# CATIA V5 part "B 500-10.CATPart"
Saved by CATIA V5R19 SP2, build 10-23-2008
Part number: B 500-10
Bounding box of the stored display mesh (mm): x -18.951 to 18.951, y -18.952 to 18.952, z 0 to 70
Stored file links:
  C:\Users\Bora\Desktop\3D Katı model\B serisi\B 500\B 500-10.CATPart
  C:\Program Files\Dassault Systemes\B19\intel_a\reffiles\standard\MetricThickPitch.txt
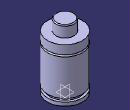
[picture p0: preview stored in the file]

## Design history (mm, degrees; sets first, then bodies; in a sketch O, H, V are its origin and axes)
Body1 (main body)
  Sketch1 on yz-plane, origin (0, 0, 0), H (0, 1, 0), V (0, 0, 1)
    point P3 (10, 69)
    point P5 (10, 69)
    point P7 (19, 48.5)
    point P8 (19, 46.5)
    point P12 (19, 46.5)
    point P13 (19, 48.5)
    line L1 (19, 0) -> (19, 4)
    line L2 (10, 69) -> (10, 58)
    arc A1 centre (9, 69) radius 1 from (10, 69) to (9, 70) ccw
    arc A2 centre (19, 47.5) radius 1 from (19, 48.5) to (19, 46.5) ccw
    line L3 (16.5, 7.5) -> (16.5, 4)
    line L4 (19, 7.5) -> (19, 46.5)
    line L5 (19, 48.5) -> (19, 58)
    line L6 (9, 70) -> (0, 70)
    point P15 (0, 70)
    line L7 (10, 58) -> (19, 58)
    line L8 (0, 0) -> (19, 0)
    line L9 (16.5, 7.5) -> (19, 7.5)
    line L10 (16.5, 4) -> (19, 4)
    tangency: L6 A1
    coincidence: P15 V, P3 P5, P7 P13, P8 P12
    horizontal: L7 H, L8 H, L9 H, L10 H
  Shaft1: profile Sketch1, axis Sketch1.V, angle 360
  Sketch2 on face of Shaft1 from Sketch1.L8, origin (0, 0, 0), H (1, 0, 0), V (0, -1, 0)
    point P1 (0, 0)
  Hole1: placed by Sketch2, at (0, 0, 0) direction (0, 0, 1), diameter 6.647, depth 7, threaded "M8", thread diameter 8, thread depth 7, pitch 1.25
